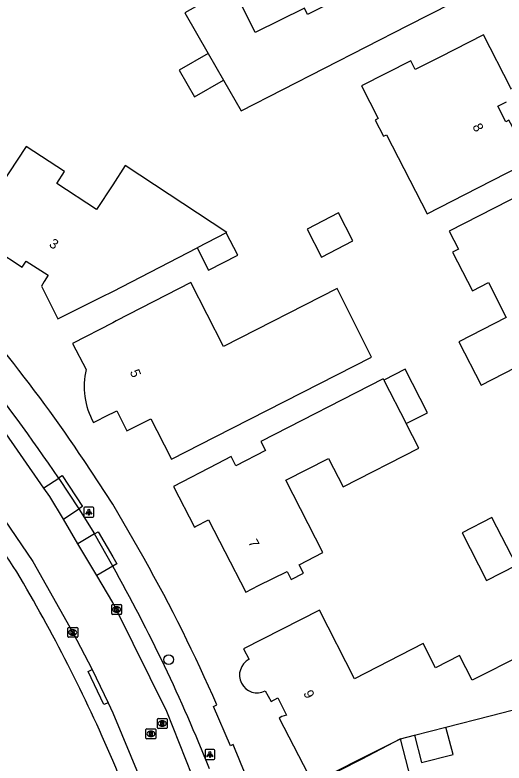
# Model space of a CAD drawing. Extents: x 158838 to 160074, y 386376 to 387776.
# Drawn here: x 159490.1 to 159539.8, y 386770.5 to 386846.6 of the extents above; entities that cross this region are included whole.
import ezdxf

# ---------------------------------------------------------------- set-up
doc = ezdxf.new("R2010")
doc.units = 0
for name, color, linetype in [('IMGEO_Boom', 7, 'Continuous'), ('IMGEO_Kolk', 7, 'Continuous'), ('IMGEO_Lichtpunt', 7, 'Continuous'), ('IMGEO_Pand', 7, 'Continuous'), ('IMGEO_Pand_nummerreeks', 7, 'Continuous'), ('IMGEO_Parkeervlak_open', 7, 'Continuous'), ('IMGEO_Rijbaan_lokaal_gesloten', 7, 'Continuous'), ('IMGEO_Rioolput', 7, 'Continuous'), ('IMGEO_Voetpad_open', 7, 'Continuous')]:
    doc.layers.add(name, color=color, linetype=linetype)

msp = doc.modelspace()

# ---------------------------------------------------------------- linework, layer by layer
at = {"layer": 'IMGEO_Boom'}
msp.add_circle((159505.696, 386781.017), 0.489, dxfattribs=at)
at = {"layer": 'IMGEO_Kolk'}
for p, q in [((159499.902, 386785.697), (159499.902, 386786.549)), ((159499.977, 386786.623), (159500.829, 386786.623)), ((159500.39, 386786.403), (159500.415, 386786.403)), ((159500.903, 386786.549), (159500.903, 386785.697)), ((159500.829, 386785.623), (159499.977, 386785.623)), ((159500.413, 386785.843), (159500.388, 386785.843)), ((159495.437, 386783.365), (159495.437, 386784.217)), ((159495.512, 386784.291), (159496.364, 386784.291)), ((159495.925, 386784.071), (159495.95, 386784.071)), ((159496.438, 386784.217), (159496.438, 386783.365)), ((159496.364, 386783.291), (159495.512, 386783.291)), ((159495.948, 386783.511), (159495.923, 386783.511))]:
    msp.add_line(p, q, dxfattribs=at)
for points in [[(159499.902, 386785.697), (159499.902, 386786.549)], [(159499.977, 386786.623), (159500.829, 386786.623)], [(159500.223, 386786.323), (159500.346, 386786.323), (159500.346, 386786.172), (159500.476, 386786.323), (159500.64, 386786.323), (159500.494, 386786.172), (159500.647, 386785.923), (159500.495, 386785.923), (159500.41, 386786.087), (159500.346, 386786.02), (159500.346, 386785.923), (159500.223, 386785.923), (159500.223, 386786.323)], [(159500.903, 386786.549), (159500.903, 386785.697)], [(159500.829, 386785.623), (159499.977, 386785.623)], [(159495.437, 386783.365), (159495.437, 386784.217)], [(159495.512, 386784.291), (159496.364, 386784.291)], [(159495.758, 386783.991), (159495.881, 386783.991), (159495.881, 386783.84), (159496.011, 386783.991), (159496.175, 386783.991), (159496.029, 386783.84), (159496.182, 386783.591), (159496.03, 386783.591), (159495.945, 386783.755), (159495.881, 386783.688), (159495.881, 386783.591), (159495.758, 386783.591), (159495.758, 386783.991)], [(159496.438, 386784.217), (159496.438, 386783.365)], [(159496.364, 386783.291), (159495.512, 386783.291)]]:
    msp.add_lwpolyline(points, dxfattribs=at)
for centre, start, end in [((159499.979, 386786.547), 91.55205, 178.44795), ((159499.979, 386786.547), 91.55205, 178.44795), ((159500.827, 386786.547), 1.55205, 88.44795), ((159500.827, 386786.547), 1.55205, 88.44795), ((159499.979, 386785.699), 181.55205, 268.44795), ((159499.979, 386785.699), 181.55205, 268.44795), ((159500.827, 386785.699), 271.55205, 358.44795), ((159500.827, 386785.699), 271.55205, 358.44795), ((159495.514, 386784.215), 91.55205, 178.44795), ((159495.514, 386784.215), 91.55205, 178.44795), ((159496.362, 386784.215), 1.55205, 88.44795), ((159496.362, 386784.215), 1.55205, 88.44795), ((159495.514, 386783.367), 181.55205, 268.44795), ((159495.514, 386783.367), 181.55205, 268.44795), ((159496.362, 386783.367), 271.55205, 358.44795), ((159496.362, 386783.367), 271.55205, 358.44795)]:
    msp.add_arc(centre, 0.0765, start, end, dxfattribs=at)
for centre, major_axis, ratio, start_param, end_param in [((159500.389, 386786.123), (-0.387, 0.002), 0.722429, 4.712389, 7.853982), ((159500.414, 386786.123), (-0.39, 0.002), 0.717154, 1.570796, 4.712389), ((159495.924, 386783.791), (-0.387, 0.002), 0.722429, 4.712389, 7.853982), ((159495.949, 386783.791), (-0.39, 0.002), 0.717154, 1.570796, 4.712389)]:
    msp.add_ellipse(centre, major_axis=major_axis, ratio=ratio, start_param=start_param, end_param=end_param, dxfattribs=at)
at = {"layer": 'IMGEO_Lichtpunt'}
for p, q in [((159497.07, 386796.434), (159497.07, 386795.627)), ((159497.07, 386796.434), (159497.07, 386795.627)), ((159497.972, 386796.529), (159497.164, 386796.529)), ((159497.972, 386796.529), (159497.164, 386796.529)), ((159498.066, 386795.627), (159498.066, 386796.434)), ((159498.066, 386795.627), (159498.066, 386796.434)), ((159497.164, 386795.533), (159497.972, 386795.533)), ((159497.164, 386795.533), (159497.972, 386795.533)), ((159509.39, 386771.764), (159509.39, 386770.957)), ((159509.39, 386771.764), (159509.39, 386770.957)), ((159510.292, 386771.859), (159509.484, 386771.859)), ((159510.292, 386771.859), (159509.484, 386771.859)), ((159510.386, 386770.957), (159510.386, 386771.764)), ((159510.386, 386770.957), (159510.386, 386771.764)), ((159509.484, 386770.863), (159510.292, 386770.863)), ((159509.484, 386770.863), (159510.292, 386770.863))]:
    msp.add_line(p, q, dxfattribs=at)
for points in [[(159497.444, 386796.098), (159497.483, 386796.07), (159497.295, 386795.808), (159497.257, 386795.835), (159497.444, 386796.098)], [(159497.546, 386796.05), (159497.593, 386796.05), (159497.593, 386795.728), (159497.546, 386795.728), (159497.546, 386796.05)], [(159497.656, 386796.07), (159497.694, 386796.097), (159497.881, 386795.835), (159497.842, 386795.807), (159497.656, 386796.07)], [(159509.764, 386771.428), (159509.803, 386771.4), (159509.615, 386771.138), (159509.577, 386771.165), (159509.764, 386771.428)], [(159509.976, 386771.4), (159510.014, 386771.427), (159510.201, 386771.165), (159510.162, 386771.137), (159509.976, 386771.4)], [(159509.866, 386771.38), (159509.913, 386771.38), (159509.913, 386771.058), (159509.866, 386771.058), (159509.866, 386771.38)]]:
    msp.add_lwpolyline(points, dxfattribs=at)
for centre in [(159497.569, 386796.232), (159509.889, 386771.562)]:
    msp.add_circle(centre, 0.0994, dxfattribs=at)
for centre, start, end in [((159497.164, 386796.434), 90, 180), ((159497.164, 386796.434), 90, 180), ((159497.972, 386796.434), 0, 90), ((159497.972, 386796.434), 0, 90), ((159497.164, 386795.627), 180, 270), ((159497.164, 386795.627), 180, 270), ((159497.972, 386795.627), 270, 0), ((159497.972, 386795.627), 270, 360), ((159509.484, 386771.764), 90, 180), ((159509.484, 386771.764), 90, 180), ((159510.292, 386771.764), 0, 90), ((159510.292, 386771.764), 0, 90), ((159509.484, 386770.957), 180, 270), ((159509.484, 386770.957), 180, 270), ((159510.292, 386770.957), 270, 0), ((159510.292, 386770.957), 270, 360)]:
    msp.add_arc(centre, 0.0946, start, end, dxfattribs=at)
at = {"layer": 'IMGEO_Pand'}
for points in [[(159527.415, 386861.393), (159527.334, 386861.569), (159522.873, 386859.312), (159517.788, 386856.876), (159520.157, 386852.058), (159520.48, 386852.216), (159522.54, 386848.026), (159519.809, 386846.683), (159519.501, 386847.31), (159514.486, 386844.844), (159512.157, 386849.581), (159507.347, 386846.829), (159509.705, 386842.716)], [(159511.264, 386839.997), (159513.062, 386836.861), (159530.038, 386845.549), (159534.489, 386847.827), (159531.714, 386853.251), (159531.484, 386853.7), (159530.727, 386853.313), (159529.477, 386855.771), (159530.124, 386856.101), (159529.884, 386856.576), (159529.376, 386857.579)], [(159540.568, 386839.059), (159540.475, 386839.239), (159537.731, 386844.612), (159533.278, 386842.338), (159530.784, 386841.065), (159530.331, 386841.96), (159525.322, 386839.422), (159527.012, 386836.085), (159526.71, 386835.93), (159527.557, 386834.274), (159527.86, 386834.429), (159531.98, 386826.383), (159537.134, 386829.042), (159541.593, 386831.304)], [(159509.705, 386842.716), (159506.744, 386841.018), (159508.303, 386838.3), (159511.264, 386839.997)], [(159509.705, 386842.716), (159511.264, 386839.997)], [(159541.968, 386832.656), (159540.461, 386835.626), (159540.313, 386835.918), (159540.01, 386835.765), (159539.187, 386837.347), (159540.055, 386837.792)], [(159511.55, 386824.447), (159511.615, 386824.481), (159501.277, 386831.291), (159500, 386829.353), (159498.333, 386826.822), (159494.299, 386829.479), (159495.089, 386830.679), (159491.185, 386833.251), (159487.629, 386827.868), (159484.267, 386826.089), (159485.793, 386825.09), (159485.386, 386824.474), (159490.802, 386820.956), (159491.199, 386821.568), (159493.429, 386820.132), (159493.031, 386819.516), (159492.741, 386819.035), (159494.41, 386815.691), (159498.884, 386817.924), (159500, 386818.499), (159508.59, 386822.923)], [(159545.237, 386829.917), (159542.961, 386828.765), (159542.776, 386829.107), (159541.808, 386828.615), (159541.857, 386828.517), (159534.233, 386824.63), (159535.174, 386822.784), (159534.586, 386822.484), (159536.591, 386818.552), (159538.231, 386819.389), (159540.041, 386815.84), (159535.208, 386813.376), (159537.482, 386808.957), (159546.791, 386813.743), (159551.236, 386816.033), (159549.365, 386819.664), (159548.942, 386820.485), (159548.558, 386820.29), (159547.633, 386822.093), (159548.89, 386822.732), (159545.237, 386829.917)], [(159519.79, 386824.838), (159521.247, 386821.992), (159524.443, 386823.628), (159522.986, 386826.474), (159519.79, 386824.838)], [(159511.55, 386824.447), (159508.59, 386822.923)], [(159508.59, 386822.923), (159509.753, 386820.666), (159512.712, 386822.19), (159511.55, 386824.447)], [(159498.043, 386805.151), (159499.65, 386805.954), (159500, 386806.129), (159500.431, 386806.344), (159501.448, 386804.289), (159503.89, 386805.512), (159504.496, 386804.324), (159505.981, 386801.414), (159510.435, 386803.687), (159526.334, 386811.801), (159522.84, 386818.777), (159511.273, 386812.872), (159507.939, 386819.402), (159500.362, 386815.485), (159500, 386815.298), (159495.92, 386813.189), (159497.283, 386810.552)], [(159529.86, 386805.036), (159532.012, 386806.143), (159529.739, 386810.562), (159527.594, 386809.475)], [(159527.594, 386809.475), (159527.526, 386809.609), (159515.061, 386803.213), (159515.536, 386802.288), (159512.538, 386800.749), (159512.063, 386801.674), (159510.622, 386800.935), (159506.173, 386798.652), (159508.303, 386794.501), (159508.425, 386794.568), (159509.73, 386795.229), (159511.407, 386792.014), (159513.55, 386787.88), (159514.845, 386788.575), (159517.737, 386789.974), (159518.141, 386789.168), (159519.421, 386789.828), (159518.986, 386790.672), (159521.386, 386791.909), (159517.623, 386799.282), (159521.966, 386801.499), (159523.439, 386798.612), (159531.134, 386802.54), (159529.86, 386805.036)], [(159527.594, 386809.475), (159529.86, 386805.036)], [(159541.073, 386790.619), (159538.583, 386795.487), (159535.545, 386793.933), (159538.036, 386789.07), (159541.073, 386790.619)], [(159543.568, 386777.779), (159541.678, 386781.505), (159536.573, 386778.916), (159535.299, 386781.43), (159532.846, 386780.187), (159531.593, 386782.645), (159524.603, 386779.08), (159521.043, 386786.061), (159513.319, 386782.124), (159513.88, 386781.048)], [(159515.523, 386777.83), (159516.106, 386776.748), (159516.793, 386777.118), (159517.674, 386775.365), (159517.218, 386775.225), (159516.944, 386775.075), (159520.361, 386768.434), (159524.817, 386770.703), (159529.272, 386772.972)], [(159533.908, 386774.16), (159538.401, 386775.312), (159544.08, 386776.768), (159543.568, 386777.779)], [(159530.701, 386773.338), (159533.908, 386774.16)], [(159530.701, 386773.338), (159531.418, 386770.545), (159534.624, 386771.367), (159533.908, 386774.16)], [(159529.272, 386772.972), (159525.268, 386770.852), (159520.812, 386768.583)], [(159529.272, 386772.972), (159530.701, 386773.338)], [(159533.64, 386755.991), (159529.272, 386772.972)]]:
    msp.add_lwpolyline(points, dxfattribs=at)
for centre, radius, start, end in [((159504.752, 386808.849), 7.661, 167.15618, 208.86335), ((159514.705, 386779.441), 1.807, 117.16791, 296.92667)]:
    msp.add_arc(centre, radius, start, end, dxfattribs=at)
at = {"layer": 'IMGEO_Parkeervlak_open'}
for points in [[(159494.508, 386799.457), (159492.993, 386798.481)], [(159494.974, 386795.299), (159496.565, 386796.378)], [(159498.135, 386793.809), (159496.45, 386792.81)], [(159500, 386790.532), (159498.373, 386789.567)]]:
    msp.add_lwpolyline(points, dxfattribs=at)
at = {"layer": 'IMGEO_Rijbaan_lokaal_gesloten'}
for points in [[(159476.07, 386812.266), (159483.819, 386802.763), (159491.887, 386790.994), (159495.94, 386783.791), (159497.901, 386780.011)], [(159492.993, 386798.481), (159488.507, 386804.877), (159484.308, 386810.039)], [(159494.974, 386795.299), (159493.598, 386797.619), (159492.993, 386798.481)], [(159496.45, 386792.81), (159494.974, 386795.299)], [(159498.373, 386789.567), (159496.45, 386792.81)], [(159508.083, 386769.223), (159505.51, 386775.732), (159500.385, 386786.098), (159500, 386786.824), (159498.373, 386789.567)], [(159497.901, 386780.011), (159499.534, 386776.61)], [(159499.534, 386776.61), (159500, 386775.598), (159504.775, 386764.163), (159505.555, 386762.056)]]:
    msp.add_lwpolyline(points, dxfattribs=at)
at = {"layer": 'IMGEO_Rioolput'}
for p, q in [((159504.539, 386774.093), (159504.539, 386774.945)), ((159504.614, 386775.019), (159505.466, 386775.019)), ((159505.027, 386774.799), (159505.052, 386774.799)), ((159505.54, 386774.945), (159505.54, 386774.093)), ((159503.384, 386773.04), (159503.384, 386773.892)), ((159503.459, 386773.966), (159504.311, 386773.966)), ((159503.872, 386773.746), (159503.897, 386773.746)), ((159504.385, 386773.892), (159504.385, 386773.04)), ((159505.466, 386774.019), (159504.614, 386774.019)), ((159505.05, 386774.239), (159505.025, 386774.239)), ((159504.311, 386772.966), (159503.459, 386772.966)), ((159503.895, 386773.186), (159503.87, 386773.186))]:
    msp.add_line(p, q, dxfattribs=at)
for points in [[(159504.539, 386774.093), (159504.539, 386774.945)], [(159504.614, 386775.019), (159505.466, 386775.019)], [(159505.128, 386774.717), (159504.876, 386774.719), (159504.876, 386774.319)], [(159504.876, 386774.319), (159505, 386774.319), (159505, 386774.481), (159505.011, 386774.481)], [(159505.054, 386774.638), (159505, 386774.638), (159505, 386774.557)], [(159505, 386774.557), (159505.052, 386774.557)], [(159505.54, 386774.945), (159505.54, 386774.093)], [(159503.384, 386773.04), (159503.384, 386773.892)], [(159503.459, 386773.966), (159504.311, 386773.966)], [(159504.385, 386773.892), (159504.385, 386773.04)], [(159505.466, 386774.019), (159504.614, 386774.019)], [(159505.058, 386774.452), (159505.129, 386774.319), (159505.269, 386774.319), (159505.204, 386774.445)], [(159504.311, 386772.966), (159503.459, 386772.966)], [(159503.973, 386773.664), (159503.721, 386773.666), (159503.721, 386773.266)], [(159503.721, 386773.266), (159503.845, 386773.266), (159503.845, 386773.428), (159503.856, 386773.428)], [(159503.899, 386773.585), (159503.845, 386773.585), (159503.845, 386773.504)], [(159503.845, 386773.504), (159503.897, 386773.504)], [(159503.903, 386773.399), (159503.974, 386773.266), (159504.114, 386773.266), (159504.049, 386773.392)]]:
    msp.add_lwpolyline(points, dxfattribs=at)
for centre, radius, start, end in [((159504.616, 386774.943), 0.0765, 91.55205, 178.44795), ((159504.616, 386774.943), 0.0765, 91.55205, 178.44795), ((159505.01, 386774.428), 0.0533, 26.02933, 88.69889), ((159505.036, 386774.746), 0.19, 274.7715, 282.96867), ((159505.06, 386774.542), 0.0964, 77.00612, 93.18647), ((159505.074, 386774.599), 0.0378, 276.66336, 79.67722), ((159505.127, 386774.607), 0.109, 350.36119, 89.41601), ((159505.125, 386774.607), 0.112, 277.58423, 350.98172), ((159505.109, 386774.392), 0.108, 29.51342, 73.79051), ((159505.464, 386774.943), 0.0765, 1.55205, 88.44795), ((159505.464, 386774.943), 0.0765, 1.55205, 88.44795), ((159503.461, 386773.89), 0.0765, 91.55205, 178.44795), ((159503.461, 386773.89), 0.0765, 91.55205, 178.44795), ((159504.309, 386773.89), 0.0765, 1.55205, 88.44795), ((159504.309, 386773.89), 0.0765, 1.55205, 88.44795), ((159504.616, 386774.095), 0.0765, 181.55205, 268.44795), ((159504.616, 386774.095), 0.0765, 181.55205, 268.44795), ((159505.464, 386774.095), 0.0765, 271.55205, 358.44795), ((159505.464, 386774.095), 0.0765, 271.55205, 358.44795), ((159503.461, 386773.042), 0.0765, 181.55205, 268.44795), ((159503.461, 386773.042), 0.0765, 181.55205, 268.44795), ((159503.855, 386773.375), 0.0533, 26.02933, 88.69889), ((159503.881, 386773.693), 0.19, 274.7715, 282.96867), ((159503.905, 386773.489), 0.0964, 77.00612, 93.18647), ((159503.919, 386773.546), 0.0378, 276.66336, 79.67722), ((159503.972, 386773.554), 0.109, 350.36119, 89.41601), ((159503.97, 386773.554), 0.112, 277.58423, 350.98172), ((159503.954, 386773.339), 0.108, 29.51342, 73.79051), ((159504.309, 386773.042), 0.0765, 271.55205, 358.44795), ((159504.309, 386773.042), 0.0765, 271.55205, 358.44795)]:
    msp.add_arc(centre, radius, start, end, dxfattribs=at)
for centre, major_axis, ratio, start_param, end_param in [((159505.026, 386774.519), (-0.387, 0.002), 0.722429, 4.712389, 7.853982), ((159505.051, 386774.519), (-0.39, 0.002), 0.717154, 1.570796, 4.712389), ((159503.871, 386773.466), (-0.387, 0.002), 0.722429, 4.712389, 7.853982), ((159503.896, 386773.466), (-0.39, 0.002), 0.717154, 1.570796, 4.712389)]:
    msp.add_ellipse(centre, major_axis=major_axis, ratio=ratio, start_param=start_param, end_param=end_param, dxfattribs=at)
at = {"layer": 'IMGEO_Voetpad_open'}
for points in [[(159503.188, 386791.299), (159500, 386796.824), (159497.087, 386801.285)], [(159494.472, 386799.51), (159494.848, 386799.752), (159496.919, 386796.618), (159496.565, 386796.378)], [(159494.472, 386799.51), (159494.508, 386799.457)], [(159494.508, 386799.457), (159496.565, 386796.378)], [(159496.565, 386796.378), (159498.135, 386793.809)], [(159498.135, 386793.809), (159498.523, 386794.023), (159500, 386791.484), (159500.407, 386790.784), (159500, 386790.532)], [(159500, 386790.532), (159498.135, 386793.809)], [(159499.534, 386776.61), (159499.109, 386776.443), (159497.495, 386779.803), (159497.901, 386780.011)], [(159512.241, 386772.367), (159511.985, 386772.236), (159510.247, 386776.232), (159510.584, 386776.402)]]:
    msp.add_lwpolyline(points, dxfattribs=at)
for centre, radius, start, end in [((159364.643, 386712.649), 159.367, 33.7916, 38.8036), ((159366.447, 386713.863), 154.032, 33.78197, 39.21359), ((159342.2, 386696.314), 175.155, 32.31336, 39.16242), ((159366.085, 386713.946), 157.419, 23.37512, 29.43146), ((159346.903, 386704.789), 175.472, 21.78758, 29.25148), ((159353.794, 386708.448), 158.922, 23.07625, 30.85061), ((159407.338, 386727.812), 113.973, 17.25528, 23.012), ((159353.521, 386708.349), 159.212, 18.6541, 23.07019)]:
    msp.add_arc(centre, radius, start, end, dxfattribs=at)

# ---------------------------------------------------------------- texts
at = {"layer": 'IMGEO_Pand_nummerreeks'}
for s, rotation, p in [('8', 297.48469, (159536.564, 386835.283)), ('3', 327.22108, (159493.447, 386823.117)), ('5', 292.08097, (159501.721, 386810.319)), ('7', 297.46535, (159513.749, 386792.961)), ('9', 296.68243, (159519.362, 386777.619))]:
    msp.add_text(s, height=1, rotation=rotation, dxfattribs=at).set_placement(p)

doc.saveas('drawing.dxf')
